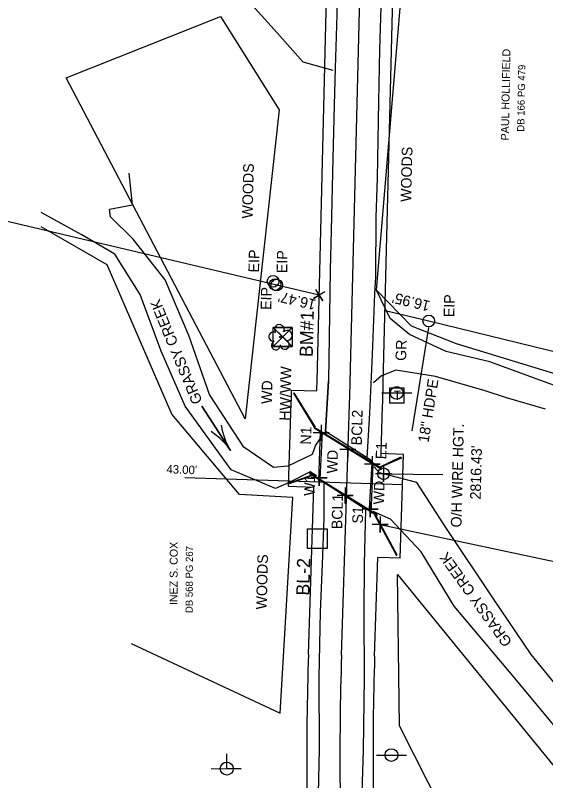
# Model space of a CAD drawing. Extents: x 1088366 to 1089341, y 781245 to 782648.
# Drawn here: x 1088731.8 to 1088931.9, y 781554.6 to 781843.2 of the extents above; entities that cross this region are included whole.
import ezdxf

# ---------------------------------------------------------------- set-up
doc = ezdxf.new("R2010")
doc.units = 0
for name, color, linetype in [('CTL Secondary Horizontal and Vertical CELL', 7, 'Continuous'), ('CTL Secondary Horizontal and Vertical Text', 7, 'Continuous'), ('CTL Vertical Benchmark CELL', 7, 'Continuous'), ('CTL Vertical Benchmark Text', 7, 'Continuous'), ('Exist DTM Spot Elevation CELL', 7, 'Continuous'), ('Exist DTM Spot Elevation Leader', 7, 'Continuous'), ('Exist DTM Spot Elevation Text', 7, 'Continuous'), ('Exist Guardrail', 7, 'Continuous'), ('Exist Guardrail Text', 7, 'Continuous'), ('Exist Horizontal Alignment', 7, 'Continuous'), ('Exist Hydro Jurisdictional Stream or Body of Water', 7, 'Continuous'), ('Exist Hydro Jurisdictional Stream or Body of Water Text', 7, 'Continuous'), ('Exist Hydro River Flow Arrow CELL', 7, 'Continuous'), ('Exist Property Corner CELL', 7, 'Continuous'), ('Exist Property Deed Book Text', 7, 'Continuous'), ('Exist Property Iron Pin CELL', 7, 'Continuous'), ('Exist Property Iron Pin Text', 7, 'Continuous'), ('Exist Property Line', 7, 'Continuous'), ('Exist Property Line Text', 7, 'Continuous'), ('Exist Property Owner Text', 7, 'Continuous'), ('Exist Right of Way Line', 7, 'Continuous'), ('Exist Right of Way Width CELL', 7, 'Continuous'), ('Exist Roads EOP', 7, 'Continuous'), ('Exist Roads Soil', 7, 'Continuous'), ('Exist Roads Soil Text', 7, 'Continuous'), ('Exist Structure Major Bridge WW', 7, 'Continuous'), ('Exist Structure Major Bridge WW Text', 7, 'Continuous'), ('Exist Structure Major Deck Tunnel Box Culvert', 7, 'Continuous'), ('Exist Structure Minor Pipes HDPE 18 Inch', 7, 'Continuous'), ('Exist Structure Minor Pipes HDPE 18 Inch Text', 7, 'Continuous'), ('Exist Utilities Other Located Object CELL', 7, 'Continuous'), ('Exist Utilities Other Located Object Leader', 7, 'Continuous'), ('Exist Utilities Other Located Object Text', 7, 'Continuous'), ('Exist Utilities Power Joint Use Telephone CELL', 7, 'Continuous'), ('Exist Utilities Telephone Pedestal CELL', 7, 'Continuous'), ('Exist Utilities Telephone Pole CELL', 7, 'Continuous'), ('Exist Vegetation Tree CELL', 7, 'Continuous'), ('Exist Vegetation Woods Line', 7, 'Continuous'), ('Exist Vegetation Woods Line Text', 7, 'Continuous')]:
    doc.layers.add(name, color=color, linetype=linetype)

msp = doc.modelspace()

# ---------------------------------------------------------------- linework, layer by layer
at = {"layer": 'CTL Secondary Horizontal and Vertical CELL'}
msp.add_line((1088845.69, 781645.8), (1088845.69, 781645.8), dxfattribs=at)
msp.add_lwpolyline([(1088841.97, 781642.15), (1088842.02, 781649.57), (1088849.44, 781649.52), (1088849.39, 781642.1)], close=True, dxfattribs=at)
at = {"layer": 'CTL Vertical Benchmark CELL'}
msp.add_line((1088832.67, 781721.91), (1088832.67, 781721.91), dxfattribs=at)
msp.add_lwpolyline([(1088829.07, 781725.5), (1088836.25, 781725.5), (1088836.25, 781718.31), (1088829.07, 781718.31)], close=True, dxfattribs=at)
for points in [[(1088836.25, 781725.5), (1088829.07, 781718.31), (1088832.66, 781721.9), (1088836.25, 781718.31), (1088829.07, 781725.5)], [(1088832.66, 781721.9), (1088836.25, 781725.5), (1088829.07, 781725.5), (1088832.66, 781721.9)], [(1088832.66, 781721.9), (1088829.07, 781718.31), (1088836.25, 781718.31), (1088832.66, 781721.9)]]:
    msp.add_lwpolyline(points, dxfattribs=at)
at = {"layer": 'Exist DTM Spot Elevation CELL'}
for points in [[(1088847.15, 781688.78), (1088847.15, 781682.78), (1088847.15, 781685.78), (1088850.15, 781685.78), (1088844.15, 781685.78)], [(1088857.25, 781682.5), (1088857.25, 781676.5), (1088857.25, 781679.5), (1088860.25, 781679.5), (1088854.25, 781679.5)], [(1088866.48, 781676.95), (1088866.48, 781670.95), (1088866.48, 781673.95), (1088869.48, 781673.95), (1088863.48, 781673.95)], [(1088870.73, 781673.31), (1088870.73, 781667.31), (1088870.73, 781670.31), (1088873.73, 781670.31), (1088867.73, 781670.31)], [(1088846.46, 781671.77), (1088846.46, 781665.77), (1088846.46, 781668.77), (1088849.46, 781668.77), (1088843.46, 781668.77)], [(1088856.28, 781665.08), (1088856.28, 781659.08), (1088856.28, 781662.08), (1088859.28, 781662.08), (1088853.28, 781662.08)], [(1088865.69, 781659.9), (1088865.69, 781653.9), (1088865.69, 781656.9), (1088868.69, 781656.9), (1088862.69, 781656.9)], [(1088869.43, 781654.14), (1088869.43, 781648.14), (1088869.43, 781651.14), (1088872.43, 781651.14), (1088866.43, 781651.14)]]:
    msp.add_lwpolyline(points, dxfattribs=at)
at = {"layer": 'Exist DTM Spot Elevation Leader'}
msp.add_lwpolyline([(1088869.43, 781651.14), (1088973.58, 781629.08), (1088973.42, 781610.13)], dxfattribs=at)
at = {"layer": 'Exist Guardrail'}
for p, q in [((1088846.81, 781686.1), (1088846.22, 781667.7)), ((1088866.04, 781655.35), (1088866.8, 781673.85))]:
    msp.add_line(p, q, dxfattribs=at)
at = {"layer": 'Exist Horizontal Alignment'}
for p, q in [((1088858.13, 781704.91), (1088864.96, 781978.89)), ((1088854.86, 781601.91), (1088857.89, 781696.39))]:
    msp.add_line(p, q, dxfattribs=at)
for centre, start, end in [((1087658.51, 781734.81), 358.16512, 358.57235), ((1090054.25, 781563.48), 178.16512, 182.91094)]:
    msp.add_arc(centre, 1200, start, end, dxfattribs=at)
at = {"layer": 'Exist Hydro Jurisdictional Stream or Body of Water'}
for points in [[(1088847.02, 781684.03), (1088845.03, 781681.1), (1088843.79, 781677.51), (1088834.59, 781673.2), (1088829.14, 781672.7), (1088818.06, 781680.38), (1088804.99, 781700.2), (1088797.29, 781722.38), (1088788.26, 781743.49), (1088776.25, 781758.78), (1088767.71, 781767.21), (1088767.26, 781770.14), (1088775.98, 781771.67), (1088774.75, 781783.61)], [(1088845.41, 781669.54), (1088843.03, 781670.97), (1088834.87, 781666.91), (1088829.93, 781664.76), (1088813.22, 781671.75), (1088795.88, 781695.84), (1088786.86, 781716.5), (1088778.89, 781737.96), (1088769.27, 781753.17), (1088756.62, 781760.53), (1088741.51, 781768.78)], [(1088953.84, 781568.58), (1088926.46, 781602.12), (1088911.94, 781623.53), (1088894.24, 781650), (1088883.33, 781666.95), (1088869.26, 781670.6), (1088867.16, 781672.95)], [(1088946.2, 781562.04), (1088920.23, 781593.24), (1088897.39, 781620.42), (1088884.95, 781640.8), (1088873.35, 781653.24), (1088866.79, 781656.11)]]:
    msp.add_lwpolyline(points, dxfattribs=at)
at = {"layer": 'Exist Hydro River Flow Arrow CELL'}
msp.add_line((1088807.58, 781687.42), (1088807.58, 781687.42), dxfattribs=at)
msp.add_lwpolyline([(1088809.51, 781688.65), (1088809.87, 781686.64), (1088810.4, 781684.63), (1088811.1, 781682.66), (1088811.95, 781680.77), (1088812.99, 781679.01), (1088802.18, 781695.83), (1088812.99, 781679.01), (1088811.82, 781680.69), (1088810.45, 781682.24), (1088808.95, 781683.7), (1088807.34, 781685.02), (1088805.66, 781686.18)], dxfattribs=at)
at = {"layer": 'Exist Property Corner CELL'}
msp.add_line((1088846.45, 781737.66), (1088846.45, 781737.66), dxfattribs=at)
msp.add_lwpolyline([(1088848.57, 781738.97), (1088844.32, 781736.34), (1088846.45, 781737.66), (1088847.76, 781735.53), (1088845.13, 781739.78)], dxfattribs=at)
at = {"layer": 'Exist Property Iron Pin CELL'}
for centre, radius in [((1088829.03, 781742.86), 2.2), ((1088829.8, 781741.66), 2.2), ((1088830.41, 781741.45), 2.2), ((1088829.03, 781742.86), 0.0707), ((1088829.8, 781741.66), 0.0707), ((1088830.41, 781741.45), 0.0707), ((1088887.78, 781727.92), 2.2), ((1088887.78, 781727.92), 0.0707)]:
    msp.add_circle(centre, radius, dxfattribs=at)
at = {"layer": 'Exist Property Line'}
for p, q in [((1088830.41, 781741.45), (1088566.16, 781803.86)), ((1088846.45, 781737.66), (1088830.41, 781741.45)), ((1088871.31, 781731.93), (1088887.78, 781727.92)), ((1088887.78, 781727.92), (1089277.34, 781633.17))]:
    msp.add_line(p, q, dxfattribs=at)
at = {"layer": 'Exist Right of Way Line'}
for p, q in [((1088845.64, 781705.22), (1088852.47, 781979.2)), ((1088870.63, 781704.6), (1088877.46, 781978.58)), ((1088836.04, 781701.81), (1088845.54, 781701.53)), ((1088834.89, 781665.59), (1088835.9, 781697.09)), ((1088869.8, 781677.88), (1088870.38, 781695.99)), ((1088878.3, 781677.61), (1088869.8, 781677.88)), ((1088877.04, 781638.41), (1088878.3, 781677.61)), ((1088834.89, 781665.59), (1088844.39, 781665.29)), ((1088842.37, 781602.31), (1088844.39, 781665.29)), ((1088867.36, 781601.51), (1088868.55, 781638.68)), ((1088877.04, 781638.41), (1088868.55, 781638.68))]:
    msp.add_line(p, q, dxfattribs=at)
for centre, radius, start, end in [((1087658.51, 781734.81), 1187.5, 358.39417, 358.57235), ((1087658.51, 781734.81), 1212.5, 358.16512, 358.57235), ((1087658.51, 781734.81), 1178, 358.16512, 358.39456), ((1090054.25, 781563.48), 1212.5, 178.16512, 182.91094), ((1090054.25, 781563.48), 1187.5, 178.16512, 182.91094)]:
    msp.add_arc(centre, radius, start, end, dxfattribs=at)
at = {"layer": 'Exist Right of Way Width CELL'}
for p in [(1088834.95, 781667.45), (1088877.93, 781666.07)]:
    msp.add_line(p, (1088795.75, 781668.71), dxfattribs=at)
at = {"layer": 'Exist Roads EOP'}
for p, q in [((1088848.76, 781686.19), (1088849.91, 781705.29)), ((1088866.36, 781675.12), (1088848.76, 781686.19)), ((1088864.04, 781656.78), (1088848.31, 781666.83))]:
    msp.add_line(p, q, dxfattribs=at)
for points in [[(1088856.86, 781979.09), (1088856.22, 781957.08), (1088855.57, 781934.3), (1088854.88, 781914.39), (1088854.52, 781894.14), (1088853.51, 781869.82), (1088853.47, 781860.13), (1088853.06, 781843.4), (1088852.42, 781823.3), (1088852.15, 781809.3), (1088851.65, 781789.26), (1088851.14, 781767.36), (1088850.59, 781747.04), (1088849.91, 781705.29), (1088848.76, 781686.19)], [(1088873.5, 781978.67), (1088872.95, 781955.77), (1088872.48, 781933.34), (1088871.73, 781914.36), (1088871.22, 781893.29), (1088870.41, 781869.88), (1088869.8, 781850.38), (1088869.18, 781830.31), (1088868.84, 781810.65), (1088868.33, 781781.83), (1088867.86, 781767.06), (1088867.68, 781744.62), (1088867.34, 781738.14), (1088866.47, 781715.27), (1088865.39, 781693.19), (1088864.42, 781676.36)], [(1088873.5, 781978.67), (1088872.95, 781955.77), (1088872.48, 781933.34), (1088871.73, 781914.36), (1088871.22, 781893.29), (1088870.41, 781869.88), (1088869.8, 781850.38), (1088869.18, 781830.31), (1088868.84, 781810.65), (1088868.33, 781781.83), (1088867.86, 781767.06), (1088867.68, 781744.62)], [(1088816.98, 781392.1), (1088825.71, 781390.34), (1088836.51, 781389.83), (1088842.4, 781393.21), (1088850.19, 781403.57), (1088852.65, 781414.78), (1088852.65, 781424.49), (1088851.88, 781433.63), (1088850.48, 781453.88), (1088848.69, 781473.37), (1088847.88, 781489.94), (1088847.11, 781512.12), (1088846.64, 781529.44), (1088846.17, 781549.67), (1088846.62, 781566.42), (1088846.42, 781593.45), (1088846.98, 781618.23), (1088847.64, 781636.22), (1088848.28, 781653.61), (1088848.31, 781666.83)], [(1088900.09, 781329.12), (1088894.18, 781340.49), (1088888.72, 781353.18), (1088882.98, 781369.77), (1088876.9, 781391.05), (1088872.78, 781412.4), (1088869.35, 781435.21), (1088867.18, 781454.87), (1088865.69, 781473.85), (1088865.05, 781490.1), (1088864.15, 781512.52), (1088863.65, 781530.36), (1088862.62, 781549.93), (1088863.18, 781566.19), (1088863.57, 781593.2), (1088863.38, 781617.88), (1088863.57, 781636.34), (1088864.04, 781656.78)]]:
    msp.add_lwpolyline(points, dxfattribs=at)
at = {"layer": 'Exist Roads Soil'}
for points in [[(1088851.73, 781822.38), (1088840.35, 781825.46), (1088830.55, 781836.64), (1088818.74, 781849.8), (1088807.48, 781868.3), (1088798.2, 781884.76), (1088783.96, 781902.06), (1088772.62, 781912.82), (1088778.19, 781927.81), (1088792.77, 781918.56), (1088802.3, 781908.7), (1088815.5, 781897.74), (1088823.39, 781881.66), (1088832.79, 781865.75), (1088826.9, 781884.58), (1088820.34, 781906.83), (1088813.13, 781929.64), (1088806.68, 781949.91), (1088799.87, 781971.84)], [(1088936.3, 781703.23), (1088910.86, 781712.46), (1088894.35, 781716.45), (1088880.49, 781722.78), (1088873.17, 781728.87), (1088868.09, 781739.51)], [(1088931.79, 781694.63), (1088917.16, 781698.96), (1088909.02, 781701.61), (1088890.39, 781706.97), (1088875.36, 781709.34), (1088869.94, 781707.23), (1088866.92, 781704.56)]]:
    msp.add_lwpolyline(points, dxfattribs=at)
at = {"layer": 'Exist Structure Major Bridge WW'}
for points in [[(1088844.97, 781687.83), (1088844.72, 781687.87), (1088836.89, 781700.68), (1088836.91, 781700.78), (1088844.97, 781687.83)], [(1088844.49, 781687.62), (1088869.97, 781672.08), (1088870.04, 781672.23), (1088844.5, 781687.79), (1088844.49, 781687.62)], [(1088843.85, 781669.69), (1088843.66, 781669.79), (1088835.23, 781666.74), (1088835.29, 781666.58), (1088843.85, 781669.69)], [(1088868.34, 781654.81), (1088842.91, 781670.51), (1088842.83, 781670.35), (1088868.29, 781654.6), (1088868.34, 781654.81)]]:
    msp.add_lwpolyline(points, dxfattribs=at)
for points in [[(1088877.48, 781676.21), (1088869.32, 781672.7), (1088869.17, 781672.84), (1088877.28, 781676.64)], [(1088875.64, 781639.45), (1088875.9, 781639.64), (1088867.68, 781654.87), (1088867.33, 781654.83)]]:
    msp.add_lwpolyline(points, close=True, dxfattribs=at)
at = {"layer": 'Exist Structure Major Deck Tunnel Box Culvert'}
msp.add_lwpolyline([(1088846.78, 781668.32), (1088847.69, 781685.9), (1088866.35, 781674.26), (1088865.35, 781657.19)], dxfattribs=at)
at = {"layer": 'Exist Structure Minor Pipes HDPE 18 Inch'}
msp.add_line((1088887.64, 781725.52), (1088881.44, 781686.48), dxfattribs=at)
at = {"layer": 'Exist Utilities Other Located Object CELL'}
for radius in [2.18, 0.24]:
    msp.add_circle((1088870.75, 781670.3), radius, dxfattribs=at)
at = {"layer": 'Exist Utilities Other Located Object Leader'}
msp.add_line((1088870.73, 781670.31), (1088893.12, 781670.07), dxfattribs=at)
at = {"layer": 'Exist Utilities Power Joint Use Telephone CELL'}
msp.add_line((1088811.56, 781559.1), (1088811.56, 781559.1), dxfattribs=at)
msp.add_lwpolyline([(1088805.62, 781559.1), (1088816.96, 781559.07), (1088811.56, 781559.08), (1088811.56, 781564.73)], dxfattribs=at)
msp.add_circle((1088811.56, 781559.11), 2.45, dxfattribs=at)
at = {"layer": 'Exist Utilities Telephone Pedestal CELL'}
msp.add_line((1088875.68, 781699.87), (1088875.68, 781699.87), dxfattribs=at)
msp.add_lwpolyline([(1088872.96, 781697.04), (1088878.55, 781697.04), (1088878.55, 781702.64), (1088872.96, 781702.64), (1088872.96, 781697.04)], dxfattribs=at)
at = {"layer": 'Exist Utilities Telephone Pole CELL'}
for p, q in [((1088870.03, 781700.79), (1088881.37, 781700.79)), ((1088875.71, 781700.79), (1088875.71, 781700.79)), ((1088868.05, 781564.2), (1088879.38, 781564.2)), ((1088873.72, 781564.2), (1088873.72, 781564.2))]:
    msp.add_line(p, q, dxfattribs=at)
for centre in [(1088875.71, 781700.79), (1088873.72, 781564.2)]:
    msp.add_circle(centre, 2.41, dxfattribs=at)
at = {"layer": 'Exist Vegetation Tree CELL'}
msp.add_line((1088831.8, 781721.86), (1088831.8, 781721.86), dxfattribs=at)
msp.add_circle((1088831.8, 781721.86), 0.326, dxfattribs=at)
for centre, radius, start, end in [((1088831.42, 781724.73), 1.86, 330.1651, 219.7134), ((1088834.35, 781722.45), 1.9, 257.1011, 134.1999), ((1088829.2, 781722.01), 1.73, 62.6636, 279.3457), ((1088830.1, 781718.74), 1.69, 111.5671, 6.231), ((1088833.47, 781718.96), 1.7, 181.2822, 74.56)]:
    msp.add_arc(centre, radius, start, end, dxfattribs=at)
at = {"layer": 'Exist Vegetation Woods Line'}
for points in [[(1088938.32, 781707.06), (1088898.21, 781719.36), (1088881.24, 781725.94), (1088868.09, 781739.51), (1088882.14, 781907.48)], [(1088775.43, 781606.28), (1088831.72, 781580.02), (1088836.44, 781661.37), (1088816.38, 781662.54), (1088790.77, 781692.76), (1088766.4, 781749.08), (1088741.58, 781763.47)], [(1088992.73, 781306.05), (1088897.1, 781404.36), (1088893.35, 781443.24), (1088904.2, 781521.06), (1088876.71, 781575.21), (1088876.03, 781632.36), (1088940.16, 781553.71)]]:
    msp.add_lwpolyline(points, dxfattribs=at)
msp.add_lwpolyline([(1088818.52, 781691.02), (1088750.92, 781819.55), (1088809.19, 781842.73), (1088831.4, 781807.58)], close=True, dxfattribs=at)

# ---------------------------------------------------------------- texts
at = {"layer": 'CTL Secondary Horizontal and Vertical Text'}
msp.add_text('BL-2', height=5, rotation=88.5723, dxfattribs=at).set_placement((1088842.75, 781624.31))
at = {"layer": 'CTL Vertical Benchmark Text'}
msp.add_text('BM#1', height=5, rotation=88.5723, dxfattribs=at).set_placement((1088844.01, 781714.27))
at = {"layer": 'Exist DTM Spot Elevation Text'}
for s, p in [('BCL2', (1088862.51, 781680.97)), ('N1', (1088843.36, 781681.26)), ('E1', (1088871.76, 781675.72)), ('W1', (1088844.71, 781661.93)), ('BCL1', (1088855.1, 781649.35)), ('S1', (1088862.9, 781651.49))]:
    msp.add_text(s, height=4, rotation=88.5723, dxfattribs=at).set_placement(p)
at = {"layer": 'Exist Guardrail Text'}
for p in [(1088853.31, 781670.37), (1088870.92, 781658.7)]:
    msp.add_text('WD', height=4, rotation=88.5722, dxfattribs=at).set_placement(p)
at = {"layer": 'Exist Hydro Jurisdictional Stream or Body of Water Text'}
for rotation, p in [(112.6384, (1088802.47, 781697.55)), (125.7407, (1088919.43, 781606.89))]:
    msp.add_text('GRASSY CREEK', height=4, rotation=rotation, dxfattribs=at).set_placement(p)
at = {"layer": 'Exist Property Deed Book Text'}
for s, rotation, p in [('DB 166 PG 479', 88.9648, (1088923.81, 781799.26)), ('DB 568 PG 267', 89.7, (1088798.69, 781617.75))]:
    msp.add_text(s, height=2.7, rotation=rotation, dxfattribs=at).set_placement(p)
at = {"layer": 'Exist Property Iron Pin Text'}
for rotation, p in [(88.9033, (1088823.74, 781746.2)), (88.9033, (1088834.36, 781745.94)), (88.9033, (1088828.34, 781732.05)), (88.3409, (1088897.38, 781729.29))]:
    msp.add_text('EIP', height=4, rotation=rotation, dxfattribs=at).set_placement(p)
at = {"layer": 'Exist Property Line Text'}
for s, rotation, p in [("16.47'", 166.7113, (1088845.53, 781735.82)), ("16.95'", 166.3294, (1088888.58, 781735.34))]:
    msp.add_text(s, height=4, rotation=rotation, dxfattribs=at).set_placement(p)
at = {"layer": 'Exist Property Owner Text'}
for s, rotation, p in [('PAUL HOLLIFIELD', 88.9648, (1088917.99, 781795.99)), ('INEZ S. COX', 89.7, (1088792.95, 781620.78))]:
    msp.add_text(s, height=3, rotation=rotation, dxfattribs=at).set_placement(p)
at = {"layer": 'Exist Right of Way Width CELL'}
msp.add_text("43.00'", height=3.2, rotation=358.1651, dxfattribs=at).set_placement((1088788.77, 781670.46))
at = {"layer": 'Exist Roads Soil Text'}
msp.add_text('GR', height=4, rotation=88.0036, dxfattribs=at).set_placement((1088879.21, 781712.81))
at = {"layer": 'Exist Structure Major Bridge WW Text'}
for s, p in [('HW/WW', (1088835.44, 781690.27)), ('WD', (1088828.59, 781696.58))]:
    msp.add_text(s, height=4, rotation=88.5723, dxfattribs=at).set_placement(p)
at = {"layer": 'Exist Structure Minor Pipes HDPE 18 Inch Text'}
msp.add_text('18" HDPE', height=4, rotation=80.9856, dxfattribs=at).set_placement((1088887.69, 781681.85))
at = {"layer": 'Exist Utilities Other Located Object Text'}
for s, p in [('O/H WIRE HGT.', (1088900.11, 781650.02)), ("2816.43'", (1088907.38, 781660.55))]:
    msp.add_text(s, height=4, rotation=88.5722, dxfattribs=at).set_placement(p)
at = {"layer": 'Exist Utilities Telephone Pedestal CELL'}
msp.add_text('T', height=3.42, dxfattribs=at).set_placement((1088874.55, 781698.16))
at = {"layer": 'Exist Vegetation Woods Line Text'}
for p in [(1088881.14, 781772.78), (1088821.29, 781766.5), (1088826.62, 781619.08)]:
    msp.add_text('WOODS', height=4, rotation=88.5722, dxfattribs=at).set_placement(p)

doc.saveas('drawing.dxf')
